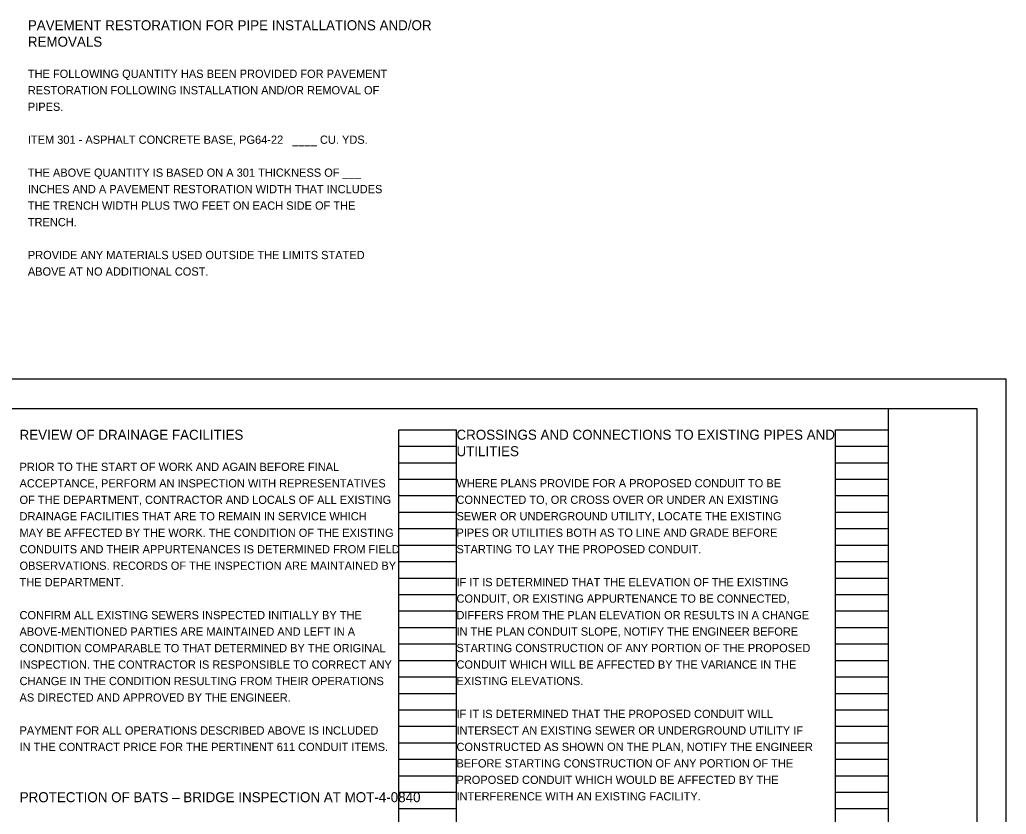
# Model space of a CAD drawing. Extents: x 0 to 52.6, y 0 to 28.5.
# Drawn here: x 17.24 to 34, y 14.6 to 28.11 of the extents above; entities that cross this region are included whole.
import ezdxf

# ---------------------------------------------------------------- set-up
doc = ezdxf.new("R2010")
doc.units = 0
for name, color, linetype in [('SH_Border', 7, 'Continuous'), ('SH_Cut_Line', 7, 'Continuous'), ('SH_Data', 7, 'Continuous'), ('SH_Text', 7, 'Continuous')]:
    doc.layers.add(name, color=color, linetype=linetype)

msp = doc.modelspace()

# ---------------------------------------------------------------- linework, layer by layer
at = {"layer": 'SH_Border'}
msp.add_line((32, 0.5), (32, 21.5), dxfattribs=at)
msp.add_lwpolyline([(1.5, 21.5), (33.5, 21.5), (33.5, 0.5), (1.5, 0.5)], close=True, dxfattribs=at)
at = {"layer": 'SH_Cut_Line'}
msp.add_lwpolyline([(0, 0), (34, 0), (34, 22), (0, 22)], close=True, dxfattribs=at)
at = {"layer": 'SH_Data'}
for p, q in [((23.68, 0.98), (23.68, 21.14)), ((23.68, 21.14), (24.66, 21.14)), ((24.66, 0.98), (24.66, 21.14)), ((31.1, 0.98), (31.1, 21.14)), ((31.1, 21.14), (32, 21.14)), ((32, 0.98), (32, 21.14)), ((23.68, 20.86), (24.66, 20.86)), ((31.1, 20.86), (32, 20.86)), ((23.68, 20.58), (24.66, 20.58)), ((31.1, 20.58), (32, 20.58)), ((23.68, 20.3), (24.66, 20.3)), ((31.1, 20.3), (32, 20.3)), ((23.68, 20.02), (24.66, 20.02)), ((31.1, 20.02), (32, 20.02)), ((23.68, 19.74), (24.66, 19.74)), ((31.1, 19.74), (32, 19.74)), ((23.68, 19.46), (24.66, 19.46)), ((31.1, 19.46), (32, 19.46)), ((23.68, 19.18), (24.66, 19.18)), ((31.1, 19.18), (32, 19.18)), ((23.68, 18.9), (24.66, 18.9)), ((31.1, 18.9), (32, 18.9)), ((23.68, 18.62), (24.66, 18.62)), ((31.1, 18.62), (32, 18.62)), ((23.68, 18.34), (24.66, 18.34)), ((31.1, 18.34), (32, 18.34)), ((23.68, 18.06), (24.66, 18.06)), ((31.1, 18.06), (32, 18.06)), ((23.68, 17.78), (24.66, 17.78)), ((31.1, 17.78), (32, 17.78)), ((23.68, 17.5), (24.66, 17.5)), ((31.1, 17.5), (32, 17.5)), ((23.68, 17.22), (24.66, 17.22)), ((31.1, 17.22), (32, 17.22)), ((23.68, 16.94), (24.66, 16.94)), ((31.1, 16.94), (32, 16.94)), ((23.68, 16.66), (24.66, 16.66)), ((31.1, 16.66), (32, 16.66)), ((23.68, 16.38), (24.66, 16.38)), ((31.1, 16.38), (32, 16.38)), ((23.68, 16.1), (24.66, 16.1)), ((31.1, 16.1), (32, 16.1)), ((23.68, 15.82), (24.66, 15.82)), ((31.1, 15.82), (32, 15.82)), ((23.68, 15.54), (24.66, 15.54)), ((31.1, 15.54), (32, 15.54)), ((23.68, 15.26), (24.66, 15.26)), ((31.1, 15.26), (32, 15.26)), ((23.68, 14.98), (24.66, 14.98)), ((31.1, 14.98), (32, 14.98)), ((23.68, 14.7), (24.66, 14.7)), ((31.1, 14.7), (32, 14.7))]:
    msp.add_line(p, q, dxfattribs=at)

# ---------------------------------------------------------------- texts
at = {"layer": 'SH_Text'}
for s, height, p in [('PAVEMENT RESTORATION FOR PIPE INSTALLATIONS AND/OR', 0.17, (17.378, 27.929)), ('REMOVALS', 0.17, (17.378, 27.649)), ('THE FOLLOWING QUANTITY HAS BEEN PROVIDED FOR PAVEMENT', 0.14, (17.378, 27.119)), ('RESTORATION FOLLOWING INSTALLATION AND/OR REMOVAL OF', 0.14, (17.378, 26.839)), ('PIPES.', 0.14, (17.378, 26.559)), ('ITEM 301 - ASPHALT CONCRETE BASE, PG64-22   ____ CU. YDS.', 0.14, (17.378, 25.999)), ('THE ABOVE QUANTITY IS BASED ON A 301 THICKNESS OF ___', 0.14, (17.378, 25.439)), ('INCHES AND A PAVEMENT RESTORATION WIDTH THAT INCLUDES', 0.14, (17.378, 25.159)), ('THE TRENCH WIDTH PLUS TWO FEET ON EACH SIDE OF THE', 0.14, (17.378, 24.879)), ('TRENCH.', 0.14, (17.378, 24.599)), ('PROVIDE ANY MATERIALS USED OUTSIDE THE LIMITS STATED', 0.14, (17.378, 24.039)), ('ABOVE AT NO ADDITIONAL COST.', 0.14, (17.378, 23.759)), ('REVIEW OF DRAINAGE FACILITIES', 0.17, (17.237, 20.969)), ('CROSSINGS AND CONNECTIONS TO EXISTING PIPES AND', 0.17, (24.66, 20.97)), ('UTILITIES', 0.17, (24.66, 20.69)), ('PRIOR TO THE START OF WORK AND AGAIN BEFORE FINAL', 0.14, (17.237, 20.439)), ('ACCEPTANCE, PERFORM AN INSPECTION WITH REPRESENTATIVES', 0.14, (17.237, 20.159)), ('WHERE PLANS PROVIDE FOR A PROPOSED CONDUIT TO BE', 0.14, (24.66, 20.16)), ('OF THE DEPARTMENT, CONTRACTOR AND LOCALS OF ALL EXISTING', 0.14, (17.237, 19.879)), ('CONNECTED TO, OR CROSS OVER OR UNDER AN EXISTING', 0.14, (24.66, 19.88)), ('DRAINAGE FACILITIES THAT ARE TO REMAIN IN SERVICE WHICH', 0.14, (17.237, 19.599)), ('SEWER OR UNDERGROUND UTILITY, LOCATE THE EXISTING', 0.14, (24.66, 19.6)), ('MAY BE AFFECTED BY THE WORK. THE CONDITION OF THE EXISTING', 0.14, (17.237, 19.319)), ('PIPES OR UTILITIES BOTH AS TO LINE AND GRADE BEFORE', 0.14, (24.66, 19.32)), ('CONDUITS AND THEIR APPURTENANCES IS DETERMINED FROM FIELD', 0.14, (17.237, 19.039)), ('STARTING TO LAY THE PROPOSED CONDUIT.', 0.14, (24.66, 19.04)), ('OBSERVATIONS. RECORDS OF THE INSPECTION ARE MAINTAINED BY', 0.14, (17.237, 18.759)), ('THE DEPARTMENT.', 0.14, (17.237, 18.479)), ('IF IT IS DETERMINED THAT THE ELEVATION OF THE EXISTING', 0.14, (24.66, 18.48)), ('CONDUIT, OR EXISTING APPURTENANCE TO BE CONNECTED,', 0.14, (24.66, 18.2)), ('CONFIRM ALL EXISTING SEWERS INSPECTED INITIALLY BY THE', 0.14, (17.237, 17.919)), ('DIFFERS FROM THE PLAN ELEVATION OR RESULTS IN A CHANGE', 0.14, (24.66, 17.92)), ('ABOVE-MENTIONED PARTIES ARE MAINTAINED AND LEFT IN A', 0.14, (17.237, 17.639)), ('IN THE PLAN CONDUIT SLOPE, NOTIFY THE ENGINEER BEFORE', 0.14, (24.66, 17.64)), ('CONDITION COMPARABLE TO THAT DETERMINED BY THE ORIGINAL', 0.14, (17.237, 17.359)), ('STARTING CONSTRUCTION OF ANY PORTION OF THE PROPOSED', 0.14, (24.66, 17.36)), ('INSPECTION. THE CONTRACTOR IS RESPONSIBLE TO CORRECT ANY', 0.14, (17.237, 17.079)), ('CONDUIT WHICH WILL BE AFFECTED BY THE VARIANCE IN THE', 0.14, (24.66, 17.08)), ('CHANGE IN THE CONDITION RESULTING FROM THEIR OPERATIONS', 0.14, (17.237, 16.799)), ('EXISTING ELEVATIONS.', 0.14, (24.66, 16.8)), ('AS DIRECTED AND APPROVED BY THE ENGINEER.', 0.14, (17.237, 16.519)), ('IF IT IS DETERMINED THAT THE PROPOSED CONDUIT WILL', 0.14, (24.66, 16.24)), ('PAYMENT FOR ALL OPERATIONS DESCRIBED ABOVE IS INCLUDED', 0.14, (17.237, 15.959)), ('INTERSECT AN EXISTING SEWER OR UNDERGROUND UTILITY IF', 0.14, (24.66, 15.96)), ('IN THE CONTRACT PRICE FOR THE PERTINENT 611 CONDUIT ITEMS.', 0.14, (17.237, 15.679)), ('CONSTRUCTED AS SHOWN ON THE PLAN, NOTIFY THE ENGINEER', 0.14, (24.66, 15.68)), ('BEFORE STARTING CONSTRUCTION OF ANY PORTION OF THE', 0.14, (24.66, 15.4)), ('PROPOSED CONDUIT WHICH WOULD BE AFFECTED BY THE', 0.14, (24.66, 15.12)), ('PROTECTION OF BATS – BRIDGE INSPECTION AT MOT-4-0840', 0.17, (17.24, 14.81)), ('INTERFERENCE WITH AN EXISTING FACILITY.', 0.14, (24.66, 14.84))]:
    msp.add_text(s, height=height, dxfattribs=at).set_placement(p)

doc.saveas('drawing.dxf')
